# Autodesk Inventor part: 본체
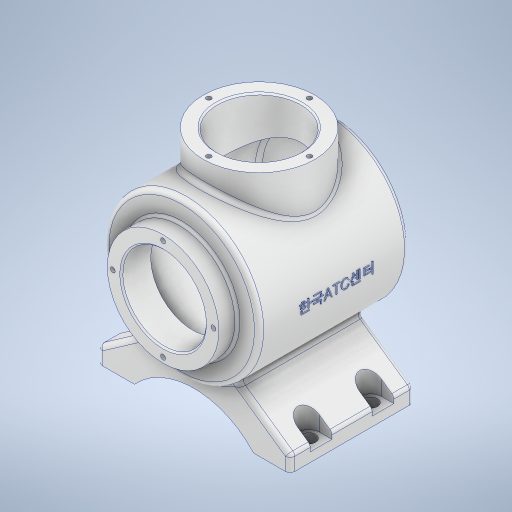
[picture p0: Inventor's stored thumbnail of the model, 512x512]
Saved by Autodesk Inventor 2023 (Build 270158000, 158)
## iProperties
Created: 2023-12
Part Number: 본체
Material: 알루미늄 6061
Document SubType Name: Modeling
Designer: asung
Density: 2.7 g/cm^3
Appearance: 알루미늄 - 평지
Mass: 1284.19 g
Surface Area: 1061.41 cm^2
Volume: 475.627 cm^3
Author: asung
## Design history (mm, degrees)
sketch "스케치1"
  geometry: L1 (0, 32.119)-(0, -87.881); L2 (37.684, 20.119)-(50, 20.119); L3 (50, 20.119)-(50, -75.697); L4 (0, 32.119)-(36, 32.119); L5 (36, 32.119)-(36, 21.803); A1 r 1.684 centre (37.684, 21.803) between (36, 21.803) and (37.684, 20.119); A2 r 113 centre (-1.051, 25.114) between (0, -87.881) and (50, -75.697); 5 further points
  constraints: 10 end point, 4 point on circle, 2 centre point, 2 tangent, 2 vertical, 1 horizontal, 1 midpoint, 1 perpendicular, 1 point on line, 1 symmetric about line, 1 vertical alignment
  dimensions: "d0" = 120 distance of L1.end L1.start; "d11" = 100 diameter of L3 L1; "d34" = 72 diameter of L5 L1; "d36" = 113 radius of A2; "d38" = 108 distance from line of L1.end L2; "d39" = 120 vertical distance of L1.end L4.end
revolve "회전1" sketch "스케치1" stored, may be unused: angle "d5" = 90 deg
sketch "스케치2"
  geometry: L1 (50, 20.119)-(50, -75.697) reference; L2 (-50, -75.697)-(-50, 20.119) reference; L3 (0, 32.119)-(0, -92.812); L4 (-36, 32.119)-(36, 32.119) reference; L5 (36, 32.119)-(36, 21.803) reference; L6 (37.684, 20.119)-(50, 20.119) reference; L7 (-50, 20.119)-(-37.684, 20.119) reference; L8 (-36, 21.803)-(-36, 32.119) reference; L9 (0, 32.119)-(27, 32.119); L10 (-36, 32.119)-(36, 32.119) reference; L11 (-50, 20.119)-(50, 20.119) reference; L12 (27, 32.119)-(27, 13.119); L13 (27, 13.119)-(40, 13.119); L14 (43, 10.119)-(43, -70.237); A1 r 1.684 centre (37.684, 21.803) between (36, 21.803) and (37.684, 20.119) reference; A2 r 1.684 centre (-37.684, 21.803) between (-37.684, 20.119) and (-36, 21.803) reference; A3 r 113 centre (-1.051, 25.114) between (0, -87.881) and (50, -75.697) reference; A4 r 113 centre (1.051, 25.114) between (-50, -75.697) and (0, -87.881) reference; A5 r 106 centre (1.051, 25.114) between (0, -80.88) and (41.134, -73.015); A6 r 3 centre (40, 10.119) between (43, 10.119) and (40, 13.119); A7 r 3 centre (40, -70.237) between (41.134, -73.015) and (43, -70.237); 5 further points
  constraints: 10 end point, 7 point on circle, 4 tangent, 3 centre point, 3 point on line, 1 equal radius, 1 horizontal, 1 midpoint, 1 perpendicular
  dimensions: "d12" = 27 distance of L3.start L9.end; "d14" = 19 distance of L9.end L12.end; "d40" = 7 radial gap between concentric circles of A4 A5; "d41" = 86 diameter of L14 L3; "d42" = 3 radius of A6 (derived)
revolve "회전2" sketch "스케치2" stored, may be unused: angle "d16" = 90 deg
node "작업 평면1"
sketch "스케치3"
  geometry: L1 (0, 0)-(0, -77); L2 (-38.5, -77)-(-62, -77); L3 (-62, -77)-(-62, -68.562); L4 (-60.721, -66.104)-(-26.694, -42.278); L5 (38.5, -77)-(62, -77); L6 (62, -77)-(62, -68.562); L7 (60.721, -66.104)-(26.694, -42.278); C1 r 42.236 at (0, 0) reference; A1 r 3 centre (-59, -68.562) between (-60.721, -66.104) and (-62, -68.562); A2 r 3 centre (59, -68.562) between (62, -68.562) and (60.721, -66.104); A3 r 52.096 centre (0, -112.096) between (38.5, -77) and (-38.5, -77); 5 further points
  constraints: 14 end point, 7 point on circle, 7 symmetric about line, 4 point on line, 3 centre point, 2 tangent, 1 horizontal, 1 perpendicular, 1 vertical, 3 other
  dimensions: "d22" = 55 deg angle of L4 L3; "d25" = 3 radius of A1 (derived); "d26" = 17 distance of L1.end point (0, -60); "d27" = 124 distance of L5.end L2.end; "d28" = 77 distance of L5.start L2.start; "d92" = 10 distance of point (62, -67) L5.end
extrude "돌출1" join sketch "스케치3" distance "d29" = 80; taper "d30" = 0 deg
fillet "모깎기1" dims "d31" = 3
fillet "모깎기2" dims "d32" = 3
node "작업 평면2"
sketch "스케치4"
  geometry: L1 (-11.926, 80)-(20.5, 80) reference; L2 (23.5, 77)-(23.5, 3) reference; L3 (15.5, 67)-(23.5, 67); L4 (15.5, 53)-(23.5, 53); C1 r 4.5 at (15.5, 60); A1 r 7 centre (15.5, 60) between (15.5, 67) and (15.5, 53); 1 further point
  constraints: 4 end point, 2 centre point, 2 perpendicular, 2 point on circle, 2 point on line, 1 coincident
  dimensions: "d44" = 9 diameter of C1; "d45" = 20 distance from line of L1 C1.centre; "d46" = 8 distance from line of L2 C1.centre; "d47" = 14 diameter of A1
extrude "돌출2" cut sketch "스케치4" distance "d48" = 80; taper "d49" = 0 deg
extrude "돌출3" cut sketch "스케치4" distance "d50" = 30; taper "d51" = 0 deg
fillet "모깎기3" dims "d55" = 3
node "작업 평면3"
sketch "스케치5"
  geometry: L1 (-74.5, 100)-(-2.5, 100) reference; C1 r 36 at (-38.5, 38); 2 further points
  constraints: 1 centre point, 1 midpoint, 1 vertical alignment
  dimensions: "d57" = 72 diameter of C1; "d58" = 62 distance from line of C1.centre L1
extrude "돌출4" join sketch "스케치5" stored distance "d59" = 30; taper "d60" = 0 deg
sketch "스케치6"
  geometry: C1 r 36 at (0, 0) reference; 2 further points
  constraints: 1 coincident
hole "구멍1" sketch "스케치6" at (0, 0) diameter "d61" = 54; stored, may be unused: countersink angle "d65" = 90 deg, drill point angle "d67" = 0 deg; dims "d62" = 6, "d63" = 4, "d64" = 2, "d66" = 50
chamfer "모따기1" distance "d68" = 1; stored, may be unused: second distance "d69" = 2, angle "d70" = 45 deg
sketch "스케치7"
  geometry: L1 (30.135, 35)-(30.135, -39) reference; C1 r 36 at (0, 0) reference; C2 r 28 at (0, 0) reference; A1 r 32.5 centre (0, 0) between (0, 32.5) and (32.5, 0); 3 further points
  constraints: 4 point on circle, 1 centre point, 1 coincident
  dimensions: "d71" = 65 diameter of A1; "d72" = 62.63545 distance from line of L1 point (-32.5, 0)
hole "구멍2" sketch "스케치7" at (0, 32.5), (32.5, 0), (0, -32.5), (-32.5, 0) diameter "d73" = 3.242; stored, may be unused: countersink angle "d77" = 90 deg, drill point angle "d79" = 118 deg; dims "d74" = 8, "d75" = 4, "d76" = 2, "d78" = 10
sketch "스케치8"
  geometry: A1 r 32.5 centre (0, 0) between (0, 32.5) and (32.5, 0); 3 further points
  constraints: 4 point on circle, 1 centre point, 1 coincident
  dimensions: "d80" = 65 diameter of A1
hole "구멍3" sketch "스케치8" at (0, 32.5), (32.5, 0), (0, -32.5), (-32.5, 0) diameter "d81" = 3.242; stored, may be unused: countersink angle "d85" = 90 deg, drill point angle "d87" = 118 deg; dims "d82" = 8, "d83" = 4, "d84" = 2, "d86" = 10
node "작업 평면4"
sketch "스케치9"
  geometry: L1 (-47, 47.908)-(47, 47.908) reference; L2 (-36, 59.908)-(36, 59.908) reference; 3 further points
  constraints: 1 midpoint, 1 vertical alignment, 1 other
  dimensions: "d88" = 62 distance from line of L2 point (0, -2.092)
feature "엠보싱1" sketch "스케치9" dims "d5" = 90 deg, "d89" = 0.5, "d90" = 0
fillet "모깎기4" dims "d91" = 3
feature "Ł耀Ń耀Ņ耀Ň耀ŉ耀ŋ耀ō耀ŏ耀" dims "d0" = 120, "d5" = 90 deg, "d11" = 100, "d12" = 27, "d14" = 19, "d16" = 90 deg, "d17" = -20, "d22" = 55 deg, "d25" = 3 (derived), "d26" = 17, "d27" = 124, "d28" = 77, "d29" = 80, "d30" = 0, "d31" = 3, "d32" = 3, "d34" = 72, "d36" = 113, "d38" = 108, "d39" = 120, "d40" = 7, "d41" = 86, "d42" = 3 (derived), "d43" = -6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
node "솔리드1"
pattern_linear "직사각형 패턴1" dims "d54" = 40
mirror "미러1"
node "투영된 루프1"
node "절단 모서리 투영1"
node "절단 모서리 투영2"
feature "A9D066F2-1C7D-4E18-AEED-F7BC21143FA4" dims "d61" = 54, "d62" = 6, "d63" = 4, "d64" = 2, "d65" = 90 deg, "d66" = 50, "d67" = 0
